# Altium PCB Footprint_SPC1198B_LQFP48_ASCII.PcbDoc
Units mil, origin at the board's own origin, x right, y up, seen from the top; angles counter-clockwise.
Board outline 6000 x 4000 mil, 2 copper layers (Top Layer, Bottom Layer); 1 components, 0 nets, 48 pads, 0 vias.
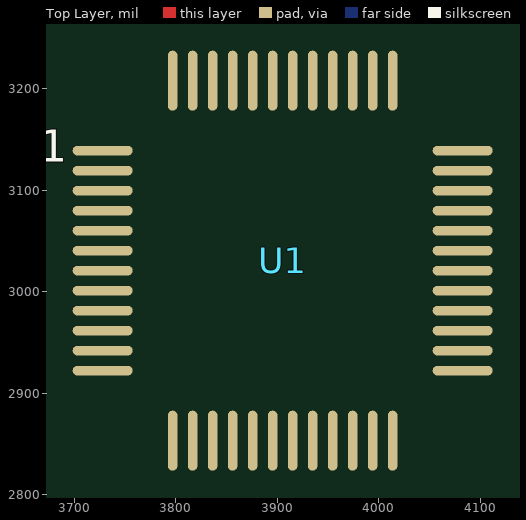
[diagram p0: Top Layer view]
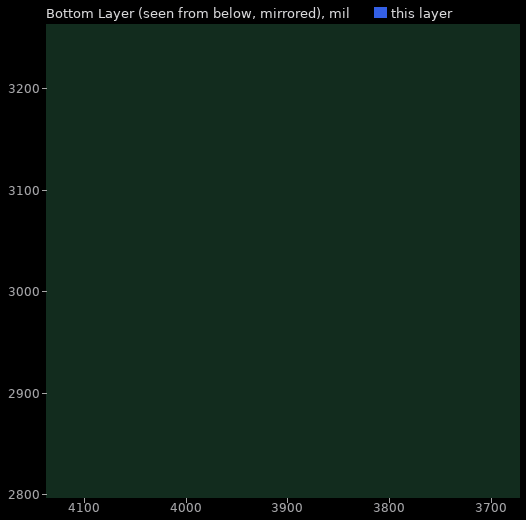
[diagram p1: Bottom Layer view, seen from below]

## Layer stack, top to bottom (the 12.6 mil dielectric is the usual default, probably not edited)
Top Solder: solder mask 0.4, Solder Resist, Dk 3.5
Top Layer: signal copper 1.4
Dielectric 1: dielectric 12.6, FR-4, Dk 4.8
Bottom Layer: signal copper 1.4
Bottom Solder: solder mask 0.4, Solder Resist, Dk 3.5

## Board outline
1000,1000 7000,1000 7000,5000 1000,5000

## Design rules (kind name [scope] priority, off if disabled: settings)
AssemblyTestPointUsage [All] p0: scope1count=1 scope1_0_kind=Board scope1_0_value=Board scope2count=1 scope2_0_kind=Board scope2_0_value=Board commentlength=0
AssemblyTestpoint [All] p0: scope1count=1 scope1_0_kind=Board scope1_0_value=Board scope2count=1 scope2_0_kind=Board scope2_0_value=Board commentlength=0
Clearance [All] p0: scope1count=1 scope1_0_kind=Board scope1_0_value=Board scope2count=1 scope2_0_kind=Board scope2_0_value=Board commentlength=0 gap=10
Clearance [All] p1: gap=10 ignorepadtopadclearanceinfootprint=FALSE except(0: Arc-Hole Track-Hole SMDPad-Hole THPad-Hole Via-Hole Fill-Hole Poly-Hole Region-Hole Text-Hole)
ComponentClearance [All] p0: scope1count=1 scope1_0_kind=Board scope1_0_value=Board scope2count=1 scope2_0_kind=Board scope2_0_value=Board commentlength=0 gap=10 collisioncheckmode=3
DiffPairsRouting [All] p0: scope1count=1 scope1_0_kind=Board scope1_0_value=Board scope2count=1 scope2_0_kind=Board scope2_0_value=Board commentlength=0
FabricationTestPointUsage [All] p0: scope1count=1 scope1_0_kind=Board scope1_0_value=Board scope2count=1 scope2_0_kind=Board scope2_0_value=Board commentlength=0 valid=0 allowmultiple=FALSE
FabricationTestpoint [All] p0: scope1count=1 scope1_0_kind=Board scope1_0_value=Board scope2count=1 scope2_0_kind=Board scope2_0_value=Board commentlength=0 side=3 testpointundercomponent=TRUE minsize=40 maxsize=100 preferedsize=60 minholesize=0 maxholesize=40 preferedholesize=32 testpointgrid=1
FanoutControl Fanout_BGA [All] p0 off: scope1count=1 scope1_0_kind=Board scope1_0_value=Board scope2count=1 scope2_0_kind=Board scope2_0_value=Board commentlength=69 // Protel DXP Scope 1 Expression Was: IsBGA   Fanout_BGA (Default Rule)
FanoutControl Fanout_LCC [All] p0 off: scope1count=1 scope1_0_kind=Board scope1_0_value=Board scope2count=1 scope2_0_kind=Board scope2_0_value=Board commentlength=69 // Protel DXP Scope 1 Expression Was: IsLCC   Fanout_LCC (Default Rule)
FanoutControl Fanout_SOIC [All] p0 off: scope1count=1 scope1_0_kind=Board scope1_0_value=Board scope2count=1 scope2_0_kind=Board scope2_0_value=Board commentlength=71 // Protel DXP Scope 1 Expression Was: IsSOIC   Fanout_SOIC (Default Rule)
FanoutControl Fanout_Small [All] p0 off: scope1count=1 scope1_0_kind=Board scope1_0_value=Board scope2count=1 scope2_0_kind=Board scope2_0_value=Board commentlength=84 // Protel DXP Scope 1 Expression Was: (CompPinCount < 5)   Fanout_Small (Default Rule)
FanoutControl Fanout_Default [All] p0: scope1count=1 scope1_0_kind=Board scope1_0_value=Board scope2count=1 scope2_0_kind=Board scope2_0_value=Board commentlength=30 // Fanout_Default (Default Rule)
Height [All] p0: scope1count=1 scope1_0_kind=Board scope1_0_value=Board scope2count=1 scope2_0_kind=Board scope2_0_value=Board commentlength=0
HoleSize [All] p0: scope1count=1 scope1_0_kind=Board scope1_0_value=Board scope2count=1 scope2_0_kind=Board scope2_0_value=Board commentlength=0 absolutevalues=TRUE maxlimit=100 minlimit=1 maxpercent=80.000 minpercent=20.000
HoleToHoleClearance [All] p0: scope1count=1 scope1_0_kind=Board scope1_0_value=Board scope2count=1 scope2_0_kind=Board scope2_0_value=Board commentlength=0
LayerPairs [All] p0: scope1count=1 scope1_0_kind=Board scope1_0_value=Board scope2count=1 scope2_0_kind=Board scope2_0_value=Board commentlength=0 enforce=TRUE
MinimumSolderMaskSliver [All] p0: scope1count=1 scope1_0_kind=Board scope1_0_value=Board scope2count=1 scope2_0_kind=Board scope2_0_value=Board commentlength=0
NetAntennae [All] p0: scope1count=1 scope1_0_kind=Board scope1_0_value=Board scope2count=1 scope2_0_kind=Board scope2_0_value=Board commentlength=0
PasteMaskExpansion [All] p0: scope1count=1 scope1_0_kind=Board scope1_0_value=Board scope2count=1 scope2_0_kind=Board scope2_0_value=Board commentlength=0 expansion=0
PlaneClearance [All] p0: scope1count=1 scope1_0_kind=Board scope1_0_value=Board scope2count=1 scope2_0_kind=Board scope2_0_value=Board commentlength=0 clearance=20
PlaneConnect [All] p0: scope1count=1 scope1_0_kind=Board scope1_0_value=Board scope2count=1 scope2_0_kind=Board scope2_0_value=Board commentlength=0 planeconnectstyle=Relief reliefexpansion=20 reliefentries=4 reliefconductorwidth=10 reliefairgap=10
PolygonConnect [All] p0: scope1count=1 scope1_0_kind=Board scope1_0_value=Board scope2count=1 scope2_0_kind=Board scope2_0_value=Board commentlength=0 connectstyle=Relief reliefconductorwidth=10 reliefentries=4 polygonreliefangle="90 Angle"
PolygonConnect [All] p1: connectstyle=Relief reliefconductorwidth=10 reliefentries=4 polygonreliefangle="90 Angle" airgapwidth=10
RoutingCorners [All] p0: scope1count=1 scope1_0_kind=Board scope1_0_value=Board scope2count=1 scope2_0_kind=Board scope2_0_value=Board commentlength=0 cornerstyle=45-Degree minsetback=100 maxsetback=100
RoutingLayers [All] p0: scope1count=1 scope1_0_kind=Board scope1_0_value=Board scope2count=1 scope2_0_kind=Board scope2_0_value=Board commentlength=0 top layer=Automatic bottom layer=Automatic
RoutingPriority [All] p0: scope1count=1 scope1_0_kind=Board scope1_0_value=Board scope2count=1 scope2_0_kind=Board scope2_0_value=Board commentlength=0
RoutingTopology [All] p0: scope1count=1 scope1_0_kind=Board scope1_0_value=Board scope2count=1 scope2_0_kind=Board scope2_0_value=Board commentlength=0 topology=Shortest
RoutingVias [All] p0: scope1count=1 scope1_0_kind=Board scope1_0_value=Board scope2count=1 scope2_0_kind=Board scope2_0_value=Board commentlength=0 holewidth=28 width=50 viastyle="Through Hole" minholewidth=28 minwidth=50 maxholewidth=28 maxwidth=50
RoutingVias [All] p1: holewidth=28 width=50 viastyle="Through Hole" minholewidth=28 minwidth=50 maxholewidth=28 maxwidth=50
ShortCircuit [All] p0: scope1count=1 scope1_0_kind=Board scope1_0_value=Board scope2count=1 scope2_0_kind=Board scope2_0_value=Board commentlength=0 allowed=FALSE
SilkToBoardRegionClearance [All] p0: scope1count=1 scope1_0_kind=Board scope1_0_value=Board scope2count=1 scope2_0_kind=Board scope2_0_value=Board commentlength=0
SilkToSilkClearance [All] p0: scope1count=1 scope1_0_kind=Board scope1_0_value=Board scope2count=1 scope2_0_kind=Board scope2_0_value=Board commentlength=0
SilkToSolderMaskClearance [All] p0 off: scope1count=1 scope1_0_kind=Board scope1_0_value=Board scope2count=1 scope2_0_kind=Board scope2_0_value=Board commentlength=44 // Protel DXP Scope 1 Expression Was: IsPad
SolderMaskExpansion [All] p0: scope1count=1 scope1_0_kind=Board scope1_0_value=Board scope2count=1 scope2_0_kind=Board scope2_0_value=Board commentlength=0 expansion=4
SolderMaskExpansion [All] p1: expansion=4 istentingtop=FALSE
UnRoutedNet [All] p0: scope1count=1 scope1_0_kind=Board scope1_0_value=Board scope2count=1 scope2_0_kind=Board scope2_0_value=Board commentlength=0
UnpouredPolygon [All] p0: scope1count=1 scope1_0_kind=Board scope1_0_value=Board scope2count=1 scope2_0_kind=Board scope2_0_value=Board commentlength=0
Width [All] p0: scope1count=1 scope1_0_kind=Board scope1_0_value=Board scope2count=1 scope2_0_kind=Board scope2_0_value=Board commentlength=0 maxlimit=10 minlimit=10 preferedwidth=10
Width [All] p1: maxlimit=10 minlimit=10 preferedwidth=10
30 further rules are at their usual default settings.

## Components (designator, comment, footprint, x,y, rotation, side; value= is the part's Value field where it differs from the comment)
U1 "" LQFP-48-0.5 3728.02,3138.84 r0 top

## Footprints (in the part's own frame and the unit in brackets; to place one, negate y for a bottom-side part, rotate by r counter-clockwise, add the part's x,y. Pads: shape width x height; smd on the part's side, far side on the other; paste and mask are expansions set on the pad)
LQFP-48-0.5 [mm] "P-0.5,7*7mm"
  oval 1.5x0.24 smd: 1(0,0) 2(0,-0.5) 3(0,-1) 4(0,-1.5) 5(0,-2) 6(0,-2.5) 7(0,-3) 8(0,-3.5) 9(0,-4) 10(0,-4.5) 11(0,-5) 12(0,-5.5) 25(9,-5.5) 26(9,-5) 27(9,-4.5) 28(9,-4) 29(9,-3.5) 30(9,-3) 31(9,-2.5) 32(9,-2) 33(9,-1.5) 34(9,-1) 35(9,-0.5) 36(9,0)
  oval 0.24x1.5 smd: 13(1.75,-7.25) 14(2.25,-7.25) 15(2.75,-7.25) 16(3.25,-7.25) 17(3.75,-7.25) 18(4.25,-7.25) 19(4.75,-7.25) 20(5.25,-7.25) 21(5.75,-7.25) 22(6.25,-7.25) 23(6.75,-7.25) 24(7.25,-7.25) 37(7.25,1.75) 38(6.75,1.75) 39(6.25,1.75) 40(5.75,1.75) 41(5.25,1.75) 42(4.75,1.75) 43(4.25,1.75) 44(3.75,1.75) 45(3.25,1.75) 46(2.75,1.75) 47(2.25,1.75) 48(1.75,1.75)

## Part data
U1: library part SPC1198B_LQFP64

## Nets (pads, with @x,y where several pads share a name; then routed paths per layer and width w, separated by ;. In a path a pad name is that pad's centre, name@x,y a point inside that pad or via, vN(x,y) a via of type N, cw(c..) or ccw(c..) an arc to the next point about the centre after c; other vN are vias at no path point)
pads on no net: U1.1 U1.2 U1.3 U1.4 U1.5 U1.6 U1.7 U1.8 U1.9 U1.10 U1.11 U1.12 U1.13 U1.14 U1.15 U1.16 U1.17 U1.18 U1.19 U1.20 U1.21 U1.22 U1.23 U1.24 U1.25 U1.26 U1.27 U1.28 U1.29 U1.30 U1.31 U1.32 U1.33 U1.34 U1.35 U1.36 U1.37 U1.38 U1.39 U1.40 U1.41 U1.42 U1.43 U1.44 U1.45 U1.46 U1.47 U1.48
